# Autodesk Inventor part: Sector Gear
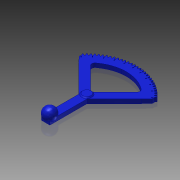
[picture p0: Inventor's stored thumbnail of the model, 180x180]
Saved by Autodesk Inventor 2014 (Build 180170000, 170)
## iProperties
Created: 2015-07
Part Number: Sector Gear
Material: Generic
Document SubType Name: Modeling
Designer: Brad Factor
Density: 1 g/cm^3
Appearance: Blue - Wall Paint - Glossy
Sending System: SolidWorks 2013
Last Author: Akzl
Author: Brad Factor
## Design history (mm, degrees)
node "Sector_Pulley"
sketch "Sketch1"
  geometry: C1 r 4.953 at (0, 0) reference; C2 r 4.953 at (0, 0); C3 r 3.239 at (0, 0)
  constraints: 2 centre point, 2 coincident, 1 concentric
  dimensions: "d0" = 6.477 diameter of C3
extrude "Shaft Adjustment" join sketch "Sketch1" stored distance "d1" = 10; taper "d2" = 0 deg
sketch "Sketch6"
  geometry: C1 r 77.153 at (0, 0); A1 r 73.025 centre (0, 0) between (-57.171, -45.433) and (57.171, -45.433) reference; 2 further points
  constraints: 2 coincident, 1 centre point, 3 other
  dimensions: "d19" = 154.305 diameter of C1
extrude "Gear Circle" join sketch "Sketch6" stored distance "d20" = 6.35; taper "d21" = 0 deg
sketch "Sketch7"
  geometry: C1 r 71.605 at (0, 0) reference; C2 r 76.2 at (0, 0) reference; C3 r 73.989 at (0, 0) reference; A1 r 77.162 centre (0, 0) between (-1.658, 77.145) and (1.658, 77.145) reference; 32 further points
  constraints: 4 centre point, 2 point on circle, 71 other
extrude "Gear Tooth" cut sketch "Sketch7" stored distance "d23" = 6.35; taper "d24" = 0 deg
sketch "Sketch10"
  geometry: L1 (-99.699, -89.265)-(-118.425, -97.654); L2 (5.654, -133.702)-(12.716, -152.967); L3 (-87.952, -84.003)-(-99.699, -89.265) reference; L4 (5.654, -133.702)-(1.224, -121.616) reference; A1 r 73.025 centre (-29.366, -69.622) between (5.654, -133.702) and (-99.699, -89.265); A2 r 73.025 centre (-29.366, -69.622) between (5.654, -133.702) and (-99.699, -89.265); A3 r 93.367 centre (-29.366, -69.622) between (12.716, -152.967) and (-118.425, -97.654); A4 r 73.025 centre (-29.366, -69.622) between (5.654, -133.702) and (-99.699, -89.265) reference; A5 r 77.153 centre (-29.366, -69.622) between (-89.907, -21.796) and (-90.631, -22.728) reference; 1 further point
  constraints: 6 point on circle, 4 end point, 3 centre point, 3 coincident, 2 collinear, 1 concentric
extrude "Gear Arc Trim" cut sketch "Sketch10" stored distance "d30" = 10; taper "d31" = 0 deg
sketch "Sketch12"
  geometry: L1 (-59.737, 105.615)-(-48.392, 93.449) reference; L2 (-6.35, 51.407)-(-48.392, 93.449) reference; L3 (-6.35, 6.476)-(-6.35, 51.407) reference; L4 (6.35, 51.407)-(6.35, 6.476) reference; L5 (48.392, 93.449)-(6.35, 51.407) reference; L6 (48.392, 93.449)-(59.737, 105.615) reference; L7 (59.305, 105.339)-(48.3, 93.537); L8 (48.3, 93.537)-(6.223, 51.46); L9 (6.223, 51.46)-(6.223, 6.771); L10 (-6.223, 6.771)-(-6.223, 51.46); L11 (-6.223, 51.46)-(-48.3, 93.537); L12 (-48.3, 93.537)-(-59.305, 105.339); L13 (-59.305, 105.339)-(-59.398, 105.252); L14 (-59.398, 105.252)-(-62.245, 108.305); L15 (59.305, 105.339)-(59.398, 105.252); L16 (59.398, 105.252)-(62.245, 108.305); A1 r 9.07 centre (0, 0) between (6.35, 6.476) and (-6.35, 6.476) reference; A2 r 77.153 centre (0, 57.43) between (58.026, 108.278) and (57.241, 109.16) reference; A3 r 77.153 centre (0, 57.43) between (54.971, 111.566) and (54.136, 112.401) reference; A4 r 77.153 centre (0, 57.43) between (51.73, 114.671) and (50.848, 115.456) reference; A5 r 77.153 centre (0, 57.43) between (48.314, 117.582) and (47.388, 118.314) reference; A6 r 77.153 centre (0, 57.43) between (44.735, 120.289) and (43.768, 120.967) reference; A7 r 77.153 centre (0, 57.43) between (41.005, 122.784) and (40, 123.404) reference; A8 r 77.153 centre (0, 57.43) between (37.135, 125.058) and (36.096, 125.618) reference; A9 r 77.153 centre (0, 57.43) between (33.14, 127.103) and (32.07, 127.602) reference; A10 r 77.153 centre (0, 57.43) between (29.033, 128.912) and (27.936, 129.348) reference; A11 r 77.153 centre (0, 57.43) between (24.828, 130.479) and (23.707, 130.85) reference; A12 r 77.153 centre (0, 57.43) between (20.538, 131.799) and (19.398, 132.104) reference; A13 r 77.153 centre (0, 57.43) between (16.179, 132.867) and (15.023, 133.106) reference; A14 r 77.153 centre (0, 57.43) between (11.766, 133.68) and (10.597, 133.851) reference; A15 r 77.153 centre (0, 57.43) between (7.312, 134.235) and (6.136, 134.338) reference; A16 r 77.153 centre (0, 57.43) between (2.834, 134.531) and (1.654, 134.565) reference; A17 r 77.153 centre (0, 57.43) between (-1.654, 134.565) and (-2.834, 134.531) reference; A18 r 77.153 centre (0, 57.43) between (-6.136, 134.338) and (-7.312, 134.235) reference; A19 r 77.153 centre (0, 57.43) between (-10.597, 133.851) and (-11.766, 133.68) reference; A20 r 77.153 centre (0, 57.43) between (-15.023, 133.106) and (-16.179, 132.867) reference; A21 r 77.153 centre (0, 57.43) between (-19.398, 132.104) and (-20.538, 131.799) reference; A22 r 77.153 centre (0, 57.43) between (-23.707, 130.85) and (-24.828, 130.479) reference; A23 r 77.153 centre (0, 57.43) between (-27.936, 129.348) and (-29.033, 128.912) reference; A24 r 77.153 centre (0, 57.43) between (-32.07, 127.602) and (-33.14, 127.103) reference; A25 r 77.153 centre (0, 57.43) between (-36.096, 125.618) and (-37.135, 125.058) reference; A26 r 77.153 centre (0, 57.43) between (-40, 123.404) and (-41.005, 122.784) reference; A27 r 77.153 centre (0, 57.43) between (-43.768, 120.967) and (-44.735, 120.289) reference; A28 r 77.153 centre (0, 57.43) between (-47.388, 118.314) and (-48.314, 117.582) reference; A29 r 77.153 centre (0, 57.43) between (-50.848, 115.456) and (-51.73, 114.671) reference; A30 r 77.153 centre (0, 57.43) between (-54.136, 112.401) and (-54.971, 111.566) reference; A31 r 77.153 centre (0, 57.43) between (-57.241, 109.16) and (-58.026, 108.278) reference; A32 r 77.026 centre (0, 57.43) between (2.743, 134.407) and (1.737, 134.436); A33 r 77.026 centre (0, 57.43) between (7.214, 134.117) and (6.212, 134.205); A34 r 77.026 centre (0, 57.43) between (11.661, 133.568) and (10.665, 133.714); A35 r 77.026 centre (0, 57.43) between (16.068, 132.761) and (15.083, 132.965); A36 r 77.026 centre (0, 57.43) between (20.421, 131.699) and (19.449, 131.96); A37 r 77.026 centre (0, 57.43) between (24.705, 130.386) and (23.75, 130.703); A38 r 77.026 centre (0, 57.43) between (28.905, 128.826) and (27.97, 129.198); A39 r 77.026 centre (0, 57.43) between (33.008, 127.025) and (32.096, 127.45); A40 r 77.026 centre (0, 57.43) between (36.998, 124.988) and (36.113, 125.465); A41 r 77.026 centre (0, 57.43) between (40.864, 122.722) and (40.007, 123.251); A42 r 77.026 centre (0, 57.43) between (44.591, 120.236) and (43.767, 120.813); A43 r 77.026 centre (0, 57.43) between (48.168, 117.537) and (47.378, 118.161); A44 r 77.026 centre (0, 57.43) between (51.581, 114.634) and (50.829, 115.303); A45 r 77.026 centre (0, 57.43) between (54.82, 111.539) and (54.108, 112.25); A46 r 77.026 centre (0, 57.43) between (57.873, 108.259) and (57.204, 109.011); A47 r 9.197 centre (0, 0) between (6.223, 6.771) and (-6.223, 6.771); A48 r 77.026 centre (0, 57.43) between (-57.204, 109.011) and (-57.873, 108.259); A49 r 77.026 centre (0, 57.43) between (-54.108, 112.25) and (-54.82, 111.539); A50 r 77.026 centre (0, 57.43) between (-50.829, 115.303) and (-51.581, 114.634); A51 r 77.026 centre (0, 57.43) between (-47.378, 118.161) and (-48.168, 117.537); A52 r 77.026 centre (0, 57.43) between (-43.767, 120.813) and (-44.591, 120.236); A53 r 77.026 centre (0, 57.43) between (-40.007, 123.251) and (-40.864, 122.722); A54 r 77.026 centre (0, 57.43) between (-36.113, 125.465) and (-36.998, 124.988); A55 r 77.026 centre (0, 57.43) between (-32.096, 127.45) and (-33.008, 127.025); A56 r 77.026 centre (0, 57.43) between (-27.97, 129.198) and (-28.905, 128.826); A57 r 77.026 centre (0, 57.43) between (-23.75, 130.703) and (-24.705, 130.386); A58 r 77.026 centre (0, 57.43) between (-19.449, 131.96) and (-20.421, 131.699); A59 r 77.026 centre (0, 57.43) between (-15.083, 132.965) and (-16.068, 132.761); A60 r 77.026 centre (0, 57.43) between (-10.665, 133.714) and (-11.661, 133.568); A61 r 77.026 centre (0, 57.43) between (-6.212, 134.205) and (-7.214, 134.117); A62 r 77.026 centre (0, 57.43) between (-1.737, 134.436) and (-2.743, 134.407); A63 r 80.391 centre (0, 57.43) between (62.245, 108.305) and (-62.245, 108.305)
  constraints: 64 point on circle, 59 concentric, 32 centre point, 20 end point, 4 perpendicular, 2 horizontal alignment, 2 parallel, 2 point on line, 1 coincident, 128 other
  dimensions: "d42" = 0.127 radial gap between concentric circles of A16 A32
extrude "Gear Tolerance Cut" cut sketch "Sketch12" stored distance "d43" = 25.4; taper "d44" = 0 deg
sketch "Sketch13"
  geometry: L1 (-59.305, 105.339)-(-59.398, 105.252) reference; L2 (-59.398, 105.252)-(-48.392, 93.449) reference; L3 (-6.35, 51.407)-(-48.392, 93.449) reference; L4 (-6.35, 6.476)-(-6.35, 51.407) reference; L5 (6.35, 51.407)-(6.35, 6.476) reference; L6 (48.392, 93.449)-(6.35, 51.407) reference; L7 (48.392, 93.449)-(59.398, 105.252) reference; L8 (59.398, 105.252)-(59.305, 105.339) reference; L9 (57.748, 103.482)-(59.995, 105.891); L10 (59.995, 105.891)-(56.63, 104.849); L11 (-57.748, 103.482)-(-60.51, 106.444); L12 (-60.51, 106.444)-(-56.63, 104.849); C1 r 3.239 at (0, 57.43) reference; A1 r 9.07 centre (0, 0) between (6.35, 6.476) and (-6.35, 6.476) reference; A2 r 77.026 centre (0, 57.43) between (57.873, 108.259) and (57.204, 109.011) reference; A3 r 77.026 centre (0, 57.43) between (54.82, 111.539) and (54.108, 112.25) reference; A4 r 77.026 centre (0, 57.43) between (51.581, 114.634) and (50.829, 115.303) reference; A5 r 77.026 centre (0, 57.43) between (48.168, 117.537) and (47.378, 118.161) reference; A6 r 77.026 centre (0, 57.43) between (44.591, 120.236) and (43.767, 120.813) reference; A7 r 77.026 centre (0, 57.43) between (40.864, 122.722) and (40.007, 123.251) reference; A8 r 77.025 centre (0, 57.43) between (36.998, 124.988) and (36.113, 125.465) reference; A9 r 77.025 centre (0, 57.43) between (33.008, 127.025) and (32.096, 127.45) reference; A10 r 77.026 centre (0, 57.43) between (28.905, 128.826) and (27.97, 129.198) reference; A11 r 77.026 centre (0, 57.43) between (24.705, 130.386) and (23.75, 130.703) reference; A12 r 77.026 centre (0, 57.43) between (20.421, 131.699) and (19.449, 131.96) reference; A13 r 77.026 centre (0, 57.43) between (16.068, 132.761) and (15.083, 132.965) reference; A14 r 77.026 centre (0, 57.43) between (11.661, 133.568) and (10.665, 133.714) reference; A15 r 77.026 centre (0, 57.43) between (7.214, 134.117) and (6.212, 134.205) reference; A16 r 77.025 centre (0, 57.43) between (2.743, 134.407) and (1.737, 134.436) reference; A17 r 77.026 centre (0, 57.43) between (-1.737, 134.436) and (-2.743, 134.407) reference; A18 r 77.026 centre (0, 57.43) between (-6.212, 134.205) and (-7.214, 134.117) reference; A19 r 77.026 centre (0, 57.43) between (-10.665, 133.714) and (-11.661, 133.568) reference; A20 r 77.026 centre (0, 57.43) between (-15.083, 132.965) and (-16.068, 132.761) reference; A21 r 77.026 centre (0, 57.43) between (-19.449, 131.96) and (-20.421, 131.699) reference; A22 r 77.026 centre (0, 57.43) between (-23.75, 130.703) and (-24.705, 130.386) reference; A23 r 77.026 centre (0, 57.43) between (-27.97, 129.198) and (-28.905, 128.826) reference; A24 r 77.026 centre (0, 57.43) between (-32.096, 127.45) and (-33.008, 127.025) reference; A25 r 77.026 centre (0, 57.43) between (-36.113, 125.465) and (-36.998, 124.988) reference; A26 r 77.026 centre (0, 57.43) between (-40.007, 123.251) and (-40.864, 122.722) reference; A27 r 77.026 centre (0, 57.43) between (-43.767, 120.813) and (-44.591, 120.236) reference; A28 r 77.026 centre (0, 57.43) between (-47.378, 118.161) and (-48.168, 117.537) reference; A29 r 77.026 centre (0, 57.43) between (-50.829, 115.303) and (-51.581, 114.634) reference; A30 r 77.026 centre (0, 57.43) between (-54.108, 112.25) and (-54.82, 111.539) reference; A31 r 77.026 centre (0, 57.43) between (-57.204, 109.011) and (-57.873, 108.259) reference; A32 r 73.862 centre (0, 57.43) between (57.748, 103.482) and (56.63, 104.849); A33 r 73.862 centre (0, 57.43) between (-56.63, 104.849) and (-57.748, 103.482)
  constraints: 8 end point, 4 point on circle, 3 point on line, 2 centre point, 2 coincident, 1 horizontal alignment, 1 perpendicular, 34 other
extrude "Partial Tooth Cut" cut sketch "Sketch13" stored distance "d45" = 25.4; taper "d46" = 0 deg
fillet "1/8\" Fillets" dims "d47" = 3.175
sketch "Sketch11"
  geometry: C1 r 3.239 at (0, 57.43) reference; C2 r 6.414 at (0, 57.43)
  constraints: 1 centre point
  dimensions: "d33" = 3.175 radial gap between concentric circles of C1 C2
extrude "Shaft Cap" join sketch "Sketch11" distance "d34" = 1.5875; taper "d35" = 0 deg
chamfer "20 mil Chamfer" distance "d36" = 0.508; stored, may be unused: second distance "d37" = 2, angle "d38" = 45 deg
chamfer "1/16\" Chamfer" distance "d39" = 1.5875; stored, may be unused: second distance "d40" = 2, angle "d41" = 45 deg
node "Cut-Extrude7"
pattern_circular "Gear Tooth Circular Pattern" dims angle "d26" = 360 deg
node "Base1"
